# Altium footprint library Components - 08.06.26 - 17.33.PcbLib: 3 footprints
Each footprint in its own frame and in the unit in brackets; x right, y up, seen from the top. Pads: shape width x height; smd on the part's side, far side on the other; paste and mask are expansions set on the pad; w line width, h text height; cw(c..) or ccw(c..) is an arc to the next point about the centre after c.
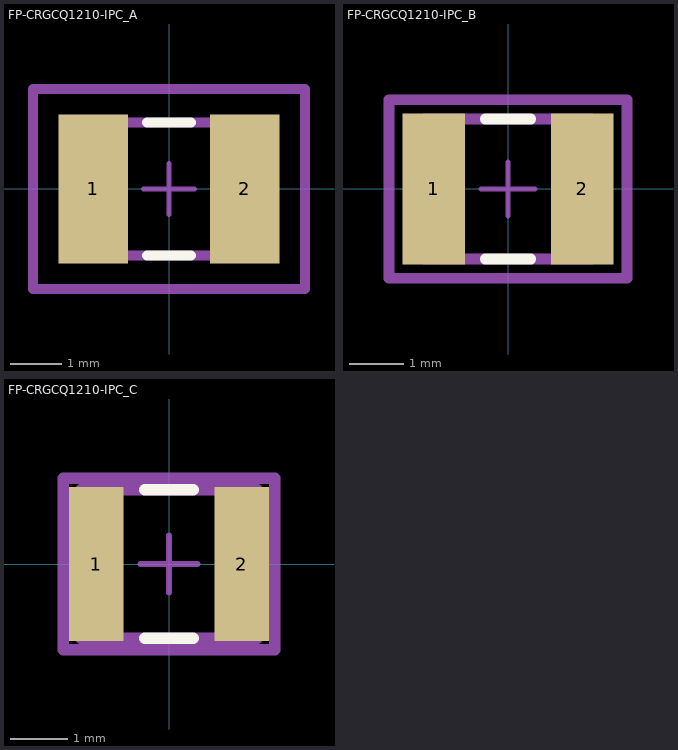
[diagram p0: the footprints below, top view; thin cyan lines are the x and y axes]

## FP-CRGCQ1210-IPC_A [mm]
pads (2):
  rect 1.358x2.906 smd paste+0 mask+0: 1(-1.477,0) 2(1.477,0)
Top Overlay:
  lines w0.2: -0.423,-1.3 0.423,-1.3 ; -0.423,1.3 0.423,1.3
Top Assembly:
  lines w0.2: -2.656,-1.953 2.656,-1.953 2.656,1.953 -2.656,1.953 -2.656,-1.953
  text ".Designator" at 0,0.188 h1
Top 3D Body:
  lines w0.2: -1.55,-1.3 1.55,-1.3 1.55,1.3 -1.55,1.3 -1.55,-1.3
Top Courtyard:
  lines w0.2: -2.656,-1.953 2.656,-1.953 2.656,1.953 -2.656,1.953 -2.656,-1.953
Top Component Center:
  lines w0.1: -0.5,0 0.5,0 ; 0,-0.5 0,0.5
3D body "Res_TE_Connectivity_CRGCQ1210F270K_eec.STEP": height 0.25, standoff 0, extent -2.656,-1.953 2.656,1.953

## FP-CRGCQ1210-IPC_B [mm]
pads (2):
  rect 1.158x2.806 smd paste+0 mask+0: 1(-1.377,0) 2(1.377,0)
Top Overlay:
  lines w0.2: -0.423,-1.3 0.423,-1.3 ; -0.423,1.3 0.423,1.3
Top Assembly:
  lines w0.2: -2.206,-1.653 2.206,-1.653 2.206,1.653 -2.206,1.653 -2.206,-1.653
  text ".Designator" at 0,0.188 h1
Top 3D Body:
  lines w0.2: -1.55,-1.3 1.55,-1.3 1.55,1.3 -1.55,1.3 -1.55,-1.3
Top Courtyard:
  lines w0.2: -2.206,-1.653 2.206,-1.653 2.206,1.653 -2.206,1.653 -2.206,-1.653
Top Component Center:
  lines w0.1: -0.5,0 0.5,0 ; 0,-0.5 0,0.5
3D body "Res_TE_Connectivity_CRGCQ1210F270K_eec.STEP": height 0.25, standoff 0, extent -2.206,-1.653 2.206,1.653

## FP-CRGCQ1210-IPC_C [mm]
pads (2):
  rect 0.958x2.706 smd paste+0 mask+0: 1(-1.277,0) 2(1.277,0)
Top Overlay:
  lines w0.2: -0.423,-1.3 0.423,-1.3 ; -0.423,1.3 0.423,1.3
Top Assembly:
  lines w0.2: -1.856,-1.5 1.856,-1.5 1.856,1.5 -1.856,1.5 -1.856,-1.5
  text ".Designator" at 0,0.188 h1
Top 3D Body:
  lines w0.2: -1.55,-1.3 1.55,-1.3 1.55,1.3 -1.55,1.3 -1.55,-1.3
Top Courtyard:
  lines w0.2: -1.856,-1.5 1.856,-1.5 1.856,1.5 -1.856,1.5 -1.856,-1.5
Top Component Center:
  lines w0.1: -0.5,0 0.5,0 ; 0,-0.5 0,0.5
3D body "Res_TE_Connectivity_CRGCQ1210F270K_eec.STEP": height 0.25, standoff 0, extent -1.856,-1.5 1.856,1.5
